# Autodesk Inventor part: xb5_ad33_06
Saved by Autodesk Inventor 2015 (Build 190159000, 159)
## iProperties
Created: 2018-05
Part Number: xb5_ad33_06
Checked By: TraceParts S.A.
Material: Generic
Catalog Web Link: www.traceparts.com
Document SubType Name: Modeling
Designer: TraceParts
Density: 1 g/cm^3
Appearance: Default
Company: TraceParts S.A.
Author: TraceParts
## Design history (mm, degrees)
feature "xb5_ad33_06.ipt"
body "Solid1"
